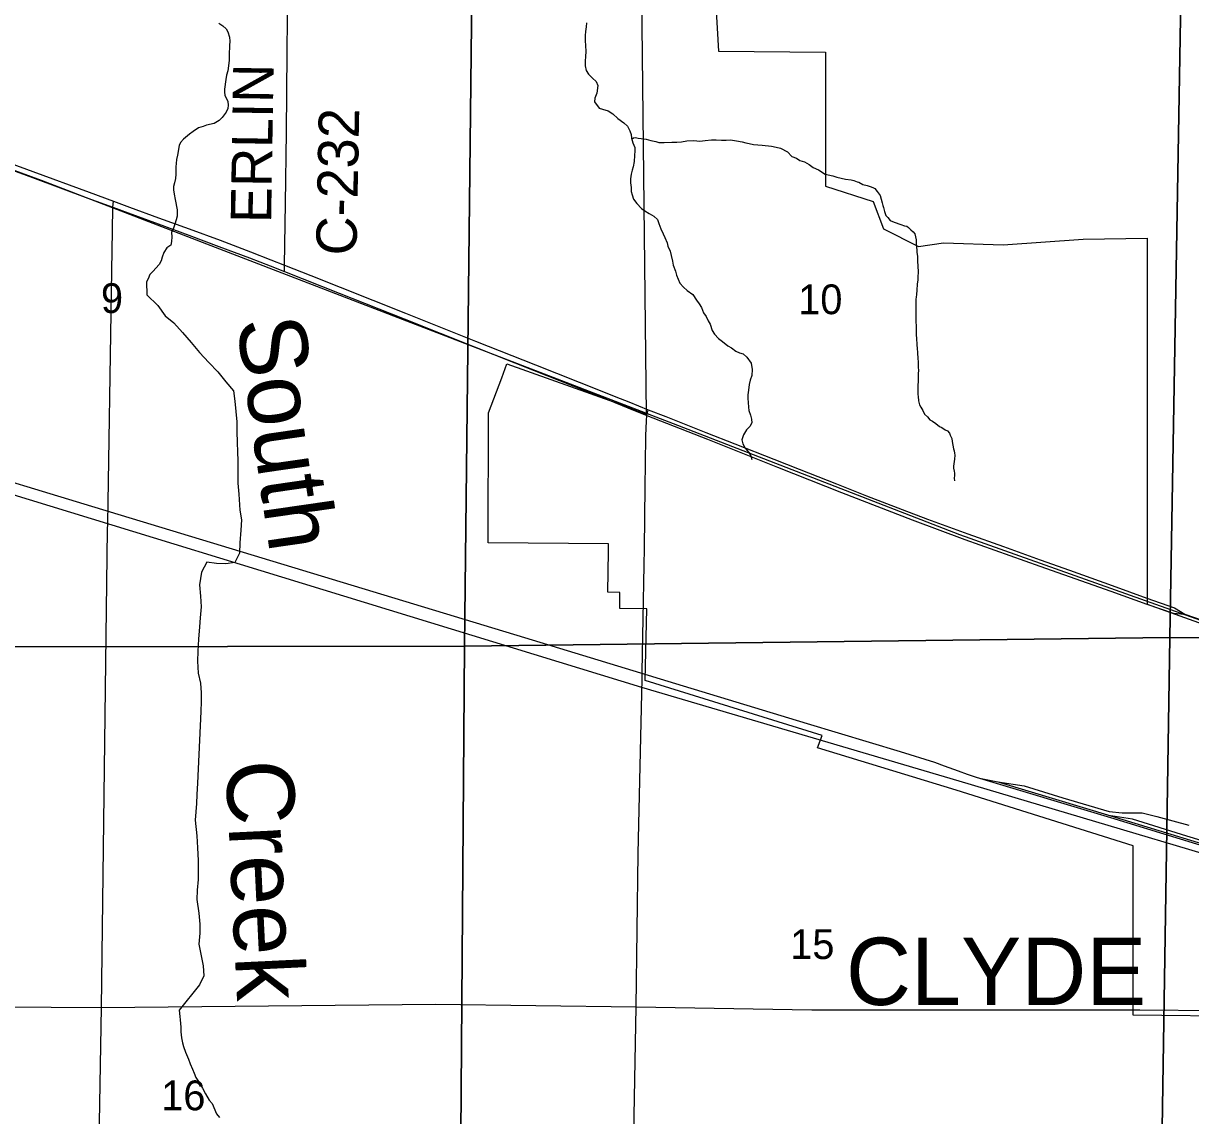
# Model space of a CAD drawing. Extents: x -8.5 to 18.7, y -20.3 to 7.
# Drawn here: x 4.267 to 7.549, y -4.076 to -1.005 of the extents above; entities that cross this region are included whole.
import ezdxf

# ---------------------------------------------------------------- set-up
doc = ezdxf.new("R2010")
doc.units = 0
for name, color, linetype in [('GM_X_Corporation', 7, 'Continuous'), ('GM_X_Corporation_Text', 7, 'Continuous'), ('GM_X_County_Road', 7, 'Continuous'), ('GM_X_County_Road_Text', 7, 'Continuous'), ('GM_X_Minor_River', 7, 'Continuous'), ('GM_X_Minor_River_Text', 7, 'Continuous'), ('GM_X_Rail_Line', 7, 'Continuous'), ('GM_X_Section', 7, 'Continuous'), ('GM_X_Section_Text', 7, 'Continuous'), ('GM_X_Township_Road', 7, 'Continuous'), ('GM_X_US_Route', 7, 'Continuous')]:
    doc.layers.add(name, color=color, linetype=linetype)

msp = doc.modelspace()

# ---------------------------------------------------------------- linework, layer by layer
at = {"layer": 'GM_X_Corporation'}
for points in [[(7.709, -3.7972), (7.387, -3.7942), (7.387, -3.3175), (6.8901, -3.1612), (6.4997, -3.0423), (6.513, -3.0072), (6.0155, -2.8525), (6.0201, -2.6518), (5.9443, -2.6505), (5.9447, -2.6051), (5.9102, -2.6047), (5.912, -2.4905), (5.9122, -2.4687), (5.5739, -2.466), (5.5749, -2.1001), (5.6124, -2.0023), (5.6262, -1.9624), (5.9293, -2.0701), (6.0195, -2.1051), (6.0042, -0.7588)], [(6.2025, -0.7592), (6.2213, -1.0838), (6.5222, -1.0867), (6.5222, -1.4627), (6.6564, -1.5063), (6.6859, -1.5834), (6.7835, -1.6331), (6.8538, -1.6219), (7.0223, -1.6278), (7.2471, -1.6121), (7.4266, -1.609), (7.4266, -2.6387), (7.7027, -2.7367)]]:
    msp.add_lwpolyline(points, dxfattribs=at)
at = {"layer": 'GM_X_County_Road'}
msp.add_line((7.406, -3.7793), (7.7303, -3.7822), dxfattribs=at)
for points in [[(5.0013, -1.7027), (5.0019, -1.6852), (5.0045, -1.5114), (5.0068, -1.3109), (5.0093, -1.0879), (5.0109, -0.8927), (5.0112, -0.7576), (5.0285, 0.2644)], [(3.4942, -3.7661), (4.4873, -3.7724), (5.4259, -3.7633), (5.9899, -3.7704)], [(5.9899, -3.7704), (6.4843, -3.7789), (7.3898, -3.7791), (7.406, -3.7793)]]:
    msp.add_lwpolyline(points, dxfattribs=at)
at = {"layer": 'GM_X_Minor_River'}
for points in [[(4.8166, -1.0045), (4.8287, -1.0122), (4.8377, -1.0206), (4.8422, -1.029), (4.8473, -1.0443), (4.8479, -1.0557), (4.847, -1.0678), (4.846, -1.0936), (4.8458, -1.1095), (4.8424, -1.1384), (4.8385, -1.1512), (4.8368, -1.1634), (4.8327, -1.1899), (4.8326, -1.1982), (4.834, -1.2081), (4.8385, -1.2165), (4.8422, -1.2249), (4.8436, -1.2355), (4.8427, -1.2446), (4.838, -1.2552), (4.8265, -1.2703), (4.8181, -1.2785), (4.8035, -1.2867), (4.7822, -1.2918), (4.7731, -1.2955), (4.7594, -1.2992), (4.7449, -1.3089), (4.7342, -1.3171), (4.7173, -1.3306), (4.7096, -1.3404), (4.7057, -1.3487), (4.7009, -1.376), (4.6984, -1.3881), (4.6968, -1.3995), (4.6959, -1.4086), (4.6957, -1.4291), (4.6948, -1.4412), (4.6924, -1.4533), (4.69, -1.4639), (4.6899, -1.473), (4.6913, -1.4859), (4.6941, -1.5004)], [(5.8507, -1.0034), (5.8498, -1.0148), (5.8482, -1.0277), (5.8465, -1.0398), (5.8471, -1.0542), (5.8477, -1.0672), (5.849, -1.0846), (5.8481, -1.0983), (5.8464, -1.1112), (5.847, -1.1249), (5.8499, -1.1378), (5.8559, -1.1485), (5.8671, -1.1592), (5.8777, -1.1684), (5.8821, -1.1799), (5.8795, -1.2019), (5.8741, -1.2155), (5.8732, -1.2261), (5.8859, -1.2437), (5.8957, -1.2468), (5.9116, -1.2516), (5.9244, -1.2593), (5.9387, -1.2731), (5.956, -1.2854), (5.9657, -1.2947), (5.9724, -1.3076), (5.9761, -1.3175), (5.9775, -1.3282), (5.9804, -1.3411), (5.9863, -1.3541), (5.9869, -1.364), (5.986, -1.3769), (5.9843, -1.3935), (5.9819, -1.4087), (5.9787, -1.4185), (5.9763, -1.4291), (5.9747, -1.4428), (5.9745, -1.4534), (5.9759, -1.4671)], [(5.978, -1.3306), (5.9826, -1.3274), (5.9879, -1.3266), (5.9963, -1.3281), (6.0039, -1.3288), (6.0183, -1.331), (6.0313, -1.3348), (6.0457, -1.3377), (6.0541, -1.34), (6.0692, -1.3399), (6.0905, -1.339), (6.1049, -1.339), (6.1178, -1.3382), (6.133, -1.3358), (6.1527, -1.3349), (6.1694, -1.3364), (6.1839, -1.3348), (6.2021, -1.3332), (6.215, -1.3324), (6.2302, -1.3338), (6.2431, -1.3338), (6.2552, -1.3329), (6.2727, -1.3351), (6.2886, -1.3381), (6.2985, -1.3411), (6.3076, -1.3426), (6.3198, -1.3455), (6.3441, -1.3477), (6.3707, -1.3506), (6.3836, -1.3536), (6.3958, -1.3566), (6.4156, -1.3664), (6.4278, -1.3792), (6.4407, -1.3845), (6.4506, -1.3905), (6.4635, -1.395), (6.4765, -1.4018), (6.4879, -1.4101), (6.5024, -1.4168), (6.5214, -1.4297), (6.5427, -1.4341), (6.5541, -1.4379), (6.5784, -1.4438), (6.5944, -1.4453), (6.602, -1.4475), (6.6111, -1.4513), (6.6164, -1.452), (6.6278, -1.458), (6.6392, -1.461), (6.6476, -1.464), (6.6552, -1.467), (6.6613, -1.47), (6.6674, -1.4776), (6.6758, -1.4897), (6.682, -1.5102), (6.6836, -1.5178), (6.6851, -1.5231), (6.6882, -1.5345), (6.692, -1.5458), (6.6981, -1.5511), (6.7043, -1.5595), (6.7157, -1.564), (6.7347, -1.5707), (6.7446, -1.5745), (6.7507, -1.5759), (6.756, -1.5797), (6.7621, -1.5858), (6.769, -1.5918), (6.7735, -1.5971), (6.7774, -1.6138), (6.7775, -1.6275), (6.7791, -1.6427), (6.7791, -1.6495), (6.7807, -1.6601), (6.7815, -1.6753), (6.7823, -1.6867), (6.7832, -1.7049), (6.7825, -1.7178), (6.7818, -1.7262), (6.7803, -1.7384), (6.7796, -1.7551), (6.7782, -1.768), (6.7775, -1.7748), (6.7767, -1.7809), (6.7761, -1.803), (6.7763, -1.8455), (6.7771, -1.8546), (6.7772, -1.8812), (6.778, -1.8918), (6.7789, -1.9085), (6.7805, -1.9207), (6.7813, -1.9298), (6.7813, -1.9351), (6.7821, -1.9442), (6.7829, -1.9609), (6.783, -1.9708), (6.7838, -1.9822), (6.7831, -1.989), (6.7832, -2.008), (6.7832, -2.0149), (6.7825, -2.0202)], [(5.9759, -1.4671), (5.9765, -1.4777), (5.9794, -1.4876), (5.9823, -1.4998), (5.9921, -1.5113), (6.0048, -1.5259), (6.0146, -1.5328), (6.0266, -1.5398), (6.0395, -1.5475), (6.05, -1.5567), (6.0536, -1.5681), (6.0595, -1.5826), (6.0662, -1.5971), (6.0706, -1.607), (6.0773, -1.6223), (6.0794, -1.6322), (6.0854, -1.6459), (6.0883, -1.6581), (6.0926, -1.6741), (6.094, -1.6855), (6.1006, -1.7022), (6.1036, -1.7137), (6.1132, -1.7358), (6.1229, -1.7473), (6.1334, -1.7565), (6.1492, -1.7673), (6.1596, -1.7833), (6.1671, -1.794), (6.1738, -1.804), (6.1797, -1.8192), (6.1872, -1.8299), (6.1924, -1.8414), (6.1983, -1.8513), (6.2042, -1.8688), (6.2109, -1.8788), (6.2221, -1.891), (6.2327, -1.8995), (6.2477, -1.9118), (6.2582, -1.918), (6.2703, -1.9272), (6.2809, -1.9312), (6.2914, -1.9343), (6.3012, -1.9435), (6.3131, -1.9611), (6.316, -1.9786), (6.315, -1.9953), (6.3111, -2.0081), (6.3079, -2.021), (6.3062, -2.0369), (6.3045, -2.0498), (6.3044, -2.0605), (6.305, -2.0711), (6.3056, -2.084), (6.3071, -2.0939), (6.3115, -2.1068), (6.3144, -2.1182), (6.3158, -2.1289), (6.3096, -2.1387), (6.3004, -2.1485), (6.2919, -2.162), (6.2871, -2.1764), (6.29, -2.1878), (6.2967, -2.2), (6.3065, -2.2115), (6.3124, -2.2215), (6.3153, -2.2314)], [(4.6941, -1.5004), (4.6963, -1.5095), (4.6984, -1.5202), (4.6999, -1.5293), (4.6996, -1.5475), (4.6973, -1.5574), (4.6933, -1.5702), (4.6894, -1.5808), (4.684, -1.5929), (4.6853, -1.6058), (4.6837, -1.6187), (4.682, -1.6286), (4.6706, -1.6368), (4.6621, -1.6496), (4.6574, -1.6625), (4.655, -1.6731), (4.6495, -1.6829), (4.6403, -1.6934), (4.6326, -1.7017), (4.6227, -1.7114), (4.618, -1.7235), (4.6135, -1.7322)], [(4.6135, -1.7322), (4.6144, -1.7683), (4.6452, -1.799), (4.6661, -1.828), (4.6909, -1.8473), (4.7149, -1.8741), (4.7396, -1.9025), (4.7628, -1.9308), (4.789, -1.9584), (4.8145, -1.9853), (4.8369, -2.0136), (4.8579, -2.0389), (4.8621, -2.0677), (4.8675, -2.1255), (4.8672, -2.1528), (4.8684, -2.184), (4.8696, -2.2098), (4.87, -2.2356), (4.8705, -2.2637), (4.8708, -2.2979), (4.8735, -2.329), (4.876, -2.3738), (4.881, -2.4012), (4.8792, -2.43), (4.8765, -2.4657), (4.8754, -2.4945), (4.8622, -2.5209), (4.8364, -2.5252), (4.8106, -2.5242), (4.7833, -2.5201), (4.7686, -2.5488), (4.7628, -2.5844), (4.7655, -2.6155), (4.7675, -2.6459), (4.7648, -2.6763), (4.763, -2.7021), (4.7596, -2.7369), (4.7584, -2.7703), (4.7566, -2.7984), (4.7592, -2.8326), (4.765, -2.86), (4.7669, -2.8873), (4.7674, -2.9124), (4.7663, -2.9404), (4.7572, -3.1415), (4.7553, -3.1734), (4.7543, -3.1992), (4.7507, -3.2454), (4.7555, -3.2895), (4.7566, -3.3237), (4.7585, -3.3586), (4.759, -3.3844), (4.7586, -3.4125), (4.756, -3.4429), (4.755, -3.4687), (4.7606, -3.5074), (4.764, -3.5378), (4.7637, -3.5629), (4.7611, -3.5947), (4.7676, -3.6267), (4.7733, -3.6556), (4.7752, -3.6837), (4.7628, -3.7086), (4.7052, -3.7802)], [(6.7825, -2.0202), (6.7818, -2.0377), (6.7819, -2.0491), (6.7826, -2.0544), (6.7842, -2.0665), (6.7866, -2.0779), (6.7904, -2.0847), (6.7965, -2.0938), (6.8011, -2.1037), (6.8095, -2.1112), (6.8156, -2.1203), (6.8232, -2.1241), (6.8331, -2.1308), (6.843, -2.1392), (6.8499, -2.1414), (6.859, -2.1482), (6.8651, -2.1512), (6.8712, -2.1573), (6.8728, -2.1633), (6.8774, -2.1724), (6.8782, -2.1808), (6.8805, -2.1914), (6.8821, -2.2013), (6.8844, -2.2073), (6.8852, -2.2142), (6.8859, -2.2195), (6.8852, -2.2309), (6.883, -2.2438), (6.8823, -2.2506), (6.8823, -2.256), (6.8839, -2.2643), (6.8847, -2.2696), (6.8847, -2.2765), (6.884, -2.2841), (6.8848, -2.2916)], [(4.7051, -3.7794), (4.7072, -3.7976), (4.7086, -3.8075), (4.7106, -3.828), (4.7105, -3.8409), (4.7118, -3.8576), (4.7147, -3.8713), (4.7176, -3.882), (4.7235, -3.898), (4.7316, -3.9178), (4.7368, -3.9308), (4.7427, -3.9453), (4.7478, -3.9567), (4.7522, -3.9689), (4.7619, -3.9834), (4.7709, -3.9995), (4.7798, -4.0147), (4.7902, -4.0331), (4.7984, -4.0423), (4.8102, -4.0712), (4.8192, -4.082)]]:
    msp.add_lwpolyline(points, dxfattribs=at)
at = {"layer": 'GM_X_Rail_Line'}
msp.add_line((6.9554, -3.1271), (7.0066, -3.1382), dxfattribs=at)
for points in [[(-3.1051, 1.2532), (-2.4469, 1.0116), (-1.5221, 0.6739), (-0.4101, 0.2634), (0.7595, -0.1688), (1.8743, -0.5688), (3.1764, -1.0285), (4.3174, -1.4463), (6.1065, -2.1352), (6.899, -2.4421), (7.8038, -2.7637), (9.1245, -3.2289), (9.8265, -3.4832)], [(-4.1359, 0.4799), (-3.9917, 0.3963), (-3.701, 0.2417), (-3.3191, 0.0535), (-3.0415, -0.0676), (-2.7956, -0.1644), (-2.5273, -0.2576), (-1.5921, -0.5518), (0.1442, -1.0771), (1.8247, -1.5912), (3.5032, -2.1053), (6.0055, -2.8718), (6.8969, -3.1354), (8.0058, -3.465), (9.3799, -3.8857)], [(3.512, -2.0746), (4.5112, -2.3783), (5.6762, -2.7323), (6.1228, -2.8677), (6.4706, -2.9734), (6.7324, -3.0525), (6.8288, -3.0829), (6.8564, -3.093), (6.8956, -3.1073), (6.9212, -3.1163), (6.9463, -3.1244), (7.3236, -3.2381), (7.7157, -3.3577)], [(7.0066, -3.1382), (7.0136, -3.1398), (7.325, -3.2337)], [(7.0066, -3.1382), (7.081, -3.1493), (7.1897, -3.1832), (7.3201, -3.2209), (7.3565, -3.2254), (7.4128, -3.2251), (7.4542, -3.2352), (7.5438, -3.2597)], [(7.9111, -3.4112), (7.8234, -3.3765), (7.5381, -3.2905), (7.3855, -3.2428), (7.325, -3.2337)], [(7.325, -3.2337), (7.717, -3.3532), (7.8865, -3.4045), (7.9111, -3.4112)]]:
    msp.add_lwpolyline(points, dxfattribs=at)
at = {"layer": 'GM_X_Section'}
for points in [[(5.5303, -0.7575), (5.5072, -2.7563), (3.5091, -2.759), (3.5254, -0.7421)], [(7.5243, -0.7725), (7.4906, -2.7325), (5.5072, -2.7563), (5.5303, -0.7575)], [(7.5243, -0.7725), (9.5232, -0.7767), (9.5129, -2.7521), (7.4906, -2.7325)], [(5.5072, -2.7563), (5.4925, -4.7558), (3.4732, -4.7592), (3.5091, -2.759)], [(7.4906, -2.7325), (7.4589, -4.7722), (5.4925, -4.7558), (5.5072, -2.7563)], [(9.5129, -2.7521), (9.4964, -4.7842), (7.4589, -4.7722), (7.4906, -2.7325)]]:
    msp.add_lwpolyline(points, close=True, dxfattribs=at)
at = {"layer": 'GM_X_Township_Road'}
for p, q in [((6.0071, -2.8282), (6.0124, -2.5282)), ((4.452, -5.7727), (4.4873, -3.7724))]:
    msp.add_line(p, q, dxfattribs=at)
for points in [[(4.5165, -1.6997), (4.5179, -1.5884), (4.5193, -1.5222), (4.5205, -1.5051)], [(4.5046, -2.4111), (4.5157, -1.7613), (4.5165, -1.6997)], [(6.0155, -2.3076), (6.0164, -2.2434), (6.0177, -2.1651), (6.0193, -2.1224), (6.0206, -2.1077), (6.0237, -2.0915)], [(6.0124, -2.5282), (6.0132, -2.4822), (6.0155, -2.3076)], [(4.4873, -3.7724), (4.5043, -2.4289), (4.5046, -2.4111)], [(5.954, -5.7639), (5.9899, -3.7704), (5.9958, -3.3393), (6.0067, -2.8482), (6.0071, -2.8282)]]:
    msp.add_lwpolyline(points, dxfattribs=at)
at = {"layer": 'GM_X_US_Route'}
for points in [[(3.5178, -1.1368), (3.6007, -1.1669), (3.6983, -1.203), (3.8863, -1.2719), (3.9705, -1.3029), (4.0851, -1.345), (4.1834, -1.3812), (4.294, -1.422), (4.4525, -1.48), (4.5205, -1.5051), (4.5662, -1.5217), (4.6475, -1.5516), (4.7336, -1.5833), (4.8208, -1.6153), (4.9062, -1.6475), (4.963, -1.6698), (5.0019, -1.6852), (5.0752, -1.7141), (5.1581, -1.7473), (5.3415, -1.8198), (5.5387, -1.8984), (5.7069, -1.965), (5.8893, -2.0373), (5.933, -2.055)], [(3.5176, -1.1544), (3.6971, -1.2199), (3.9232, -1.303), (4.1084, -1.3713), (4.2928, -1.4389), (4.4487, -1.4964), (4.5193, -1.5222), (4.5619, -1.5376), (4.6469, -1.5691), (4.7331, -1.6008), (4.8174, -1.6323), (4.9029, -1.6648), (4.961, -1.6871), (5.0013, -1.7027), (5.1551, -1.7636), (5.3384, -1.8361), (5.5356, -1.9147), (5.7038, -1.9813), (5.8862, -2.0536), (5.93, -2.0713)], [(5.933, -2.055), (5.9695, -2.0697), (6.0237, -2.0915)], [(5.93, -2.0713), (5.9665, -2.086), (6.0206, -2.1077), (6.1904, -2.174), (6.2091, -2.1815)], [(6.0237, -2.0915), (6.0735, -2.1108), (6.1859, -2.1553), (6.268, -2.1878), (6.3776, -2.2308), (6.4485, -2.2585), (6.5534, -2.2996), (6.6382, -2.3334), (6.7378, -2.3723), (6.809, -2.3989), (6.923, -2.4406), (7.0232, -2.4763), (7.126, -2.5134), (7.208, -2.5426), (7.3285, -2.5859), (7.4256, -2.621), (7.5037, -2.649), (7.5325, -2.6664)], [(6.2091, -2.1815), (6.388, -2.2527), (6.5677, -2.324), (6.7659, -2.4014), (6.9144, -2.4562), (7.1246, -2.5319), (7.3242, -2.6022), (7.4259, -2.6384), (7.4995, -2.6634), (7.5325, -2.6664)], [(7.5325, -2.6664), (7.7005, -2.7242), (7.8894, -2.7896), (8.0169, -2.8342), (8.0737, -2.8547)]]:
    msp.add_lwpolyline(points, dxfattribs=at)

# ---------------------------------------------------------------- texts
at = {"layer": 'GM_X_Corporation_Text'}
msp.add_text('CLYDE', height=0.18939, rotation=0, dxfattribs=at).set_placement((6.58, -3.7654))
at = {"layer": 'GM_X_County_Road_Text'}
for s, rotation, p in [('ERLIN', 89.0651, (4.9639, -1.5674)), ('C-232', 88.8978, (5.2039, -1.6586))]:
    msp.add_text(s, height=0.11364, rotation=rotation, dxfattribs=at).set_placement(p)
at = {"layer": 'GM_X_Minor_River_Text'}
for s, rotation, p in [('South', 278.2239, (4.866, -1.842)), ('Creek', 272.7558, (4.8358, -3.0805))]:
    msp.add_text(s, height=0.18948, rotation=rotation, dxfattribs=at).set_placement(p)
at = {"layer": 'GM_X_Section_Text'}
for s, height, p in [('9', 0.0837, (4.4856, -1.8197)), ('10', 0.08371, (6.4456, -1.823)), ('15', 0.08371, (6.4231, -3.6361)), ('16', 0.08371, (4.6548, -4.0613))]:
    msp.add_text(s, height=height, rotation=0, dxfattribs=at).set_placement(p)

doc.saveas('drawing.dxf')
